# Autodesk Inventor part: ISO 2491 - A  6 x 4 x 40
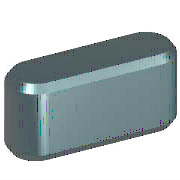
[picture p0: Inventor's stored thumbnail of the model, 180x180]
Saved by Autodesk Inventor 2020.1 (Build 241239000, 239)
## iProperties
Created: 2019-01
Part Number: ISO 2491 - A  6 x 4 x 40
Material: Stahl, weich
Description: Passfedern
Document SubType Name: Modeling
Standard: ISO 2491
Designer: lutzd
Standard Revision: First edition 1974-08-15
Standards Organization: ISO
Language: de-DE
Size Designation: A  6 x 4 x 40
Categories: <MemberInstance><Categories><Category DisplayName="Wellenteile" InternalName="7f7aeb1f-a693-4053-b835-cee3144e0d98" Mnemonic="SHFT"><Category DisplayName="Passf
Mass: 7.18538 g
Surface Area: 7.7083 cm^2
Volume: 0.915335 cm^3
Density: 7.85 g/cm^3
Appearance: Halbpoliert
IsCustomPart: 0
Author: lutzd
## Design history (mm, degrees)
workplane "Work Plane1"
workplane "Work Plane2"
sketch "Skizze1"
  geometry: L1 (3, 3)-(37, 3); L2 (37, -3)-(3, -3); L3 (0, 9.4)-(0, -7.4) reference; L4 (-5, 0)-(30, 0) reference; L5 (40, 0)-(40, 7); A1 r 3 centre (3, 0) between (3, 3) and (3, -3); A2 r 3 centre (37, 0) between (37, -3) and (37, 3)
  constraints: 6 end point, 5 point on circle, 4 tangent, 3 point on line, 2 centre point, 1 horizontal, 1 parallel, 1 perpendicular
  dimensions: "d0" = 3 radius of A1 (= 0.5 x PB); "d13" = 3 radius of A2 (= 0.5 x PB); "d14" = 40 distance between parallel lines of L5 L3 (= NLG)
extrude "Körper1" new body sketch "Skizze1" taper "d3" = 0 deg; stored distance "d4" = 10
workplane "Work Plane3"
body "Solid1"
chamfer "Fase1" distance "d8" = 0.4 (= PHH); stored, may be unused: second distance "d9" = 0.4 (= PHH), angle "d15" = 45 deg
other parameters: "d1" = -2.5 (= -PNT), "d2" = 1.5 (= PH - PNT), "NLG" = 40 [user parameter; used in 1 equation term], "PB" = 6 [user parameter; used in 2 equation terms], "PNT" = 2.5 [user parameter; used in 2 equation terms], "PH" = 4 [user parameter; used in 1 equation term], "PHH" = 0.4 [user parameter; used in 2 equation terms], "d10" = 0, "d16" = 0, "d17" = 0, "d18" = 0, "RR" = 0.16 [user parameter], "WDMIN" = 17 [user parameter], "WDMAX" = 22 [user parameter], "PUEB" = 1.8 [user parameter]
